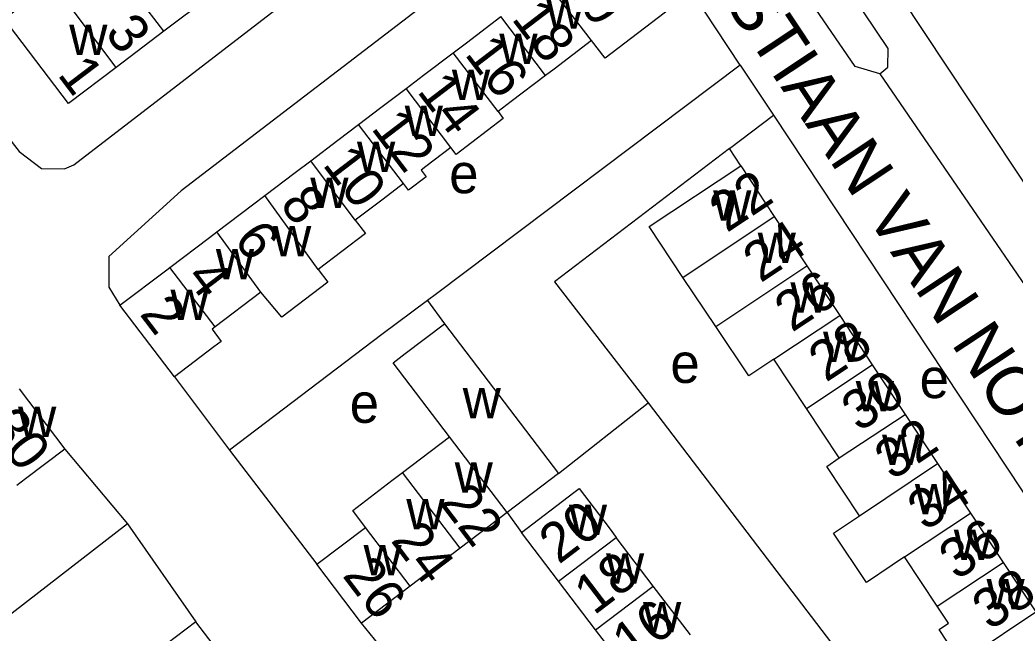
# Model space of a CAD drawing. Extents: x 159294 to 161936, y 384538 to 386517.
# Drawn here: x 160545.6 to 160646.3, y 385616.7 to 385678.8 of the extents above; entities that cross this region are included whole.
import ezdxf

# ---------------------------------------------------------------- set-up
doc = ezdxf.new("R2010")
doc.units = 0
for name, color, linetype in [('BLT_Basislijn', 7, 'Continuous'), ('BLT_Bebouwing', 7, 'Continuous'), ('BLT_Centroide', 7, 'Continuous'), ('BLT_Huisnummer', 7, 'Continuous'), ('BLT_Huisnummer_ tussenligend', 7, 'Continuous'), ('BLT_Onderverdeling_panden', 7, 'Continuous'), ('BLT_Straatnaam', 7, 'Continuous')]:
    doc.layers.add(name, color=color, linetype=linetype)

msp = doc.modelspace()

# ---------------------------------------------------------------- linework, layer by layer
at = {"layer": 'BLT_Basislijn'}
for p, q in [((160614.12, 385712.33), (160652.81, 385653.8)), ((160621.87, 385669.13), (160661.46, 385609.26)), ((160586.82, 385650.35), (160588.57, 385648.01)), ((160561.21, 385642.62), (160566.8, 385635.19)), ((160600.1, 385632.84), (160609.18, 385639.98)), ((160609.18, 385639.98), (160643.03, 385595.64)), ((160550.12, 385635.3), (160556.46, 385627.73)), ((160566.8, 385635.19), (160575.64, 385623.64)), ((160594.89, 385628.88), (160596.35, 385626.86)), ((160556.46, 385627.73), (160563.39, 385617.82))]:
    msp.add_line(p, q, dxfattribs=at)
for points in [[(160632.62, 385673.31), (160633.46, 385673.99), (160633.47, 385675.88), (160618.35, 385698.41), (160617.55, 385699.02), (160616.69, 385698.62), (160614.58, 385696.77)], [(160632.62, 385673.31), (160630.13, 385674.05), (160614.58, 385696.77)], [(160532.44, 385682.31), (160545.5, 385665.46), (160547.76, 385663.73), (160550.07, 385663.68), (160551.02, 385664.1), (160586.59, 385691.5), (160587.15, 385692.07)], [(160618.51, 385674.18), (160607.54, 385690.84), (160605.7, 385692.47), (160603.08, 385692.63), (160599.58, 385690.36), (160561.89, 385661.48), (160554.58, 385654.82), (160554.58, 385651.72), (160555.69, 385649.88)], [(160618.51, 385674.18), (160587.75, 385651.05), (160586.82, 385650.35)], [(160618.51, 385674.18), (160621.87, 385669.13)], [(160632.62, 385673.31), (160651.04, 385646.48), (160650.69, 385642), (160655.84, 385634.31)], [(160617.4, 385665.74), (160621.87, 385669.13)], [(160617.4, 385665.74), (160599.68, 385652.26), (160609.18, 385639.98)], [(160618.56, 385663.99), (160617.4, 385665.74)], [(160586.82, 385650.35), (160582.22, 385646.93), (160566.8, 385635.19)], [(160556.46, 385627.73), (160500, 385584), (160498.36, 385582.75)], [(160592.36, 385601.72), (160581.48, 385616.05), (160580.16, 385617.69)]]:
    msp.add_lwpolyline(points, dxfattribs=at)
at = {"layer": 'BLT_Bebouwing'}
for p, q in [((160564.99, 385681.29), (160560.15, 385677.63)), ((160590.78, 385676.47), (160594.26, 385679.11)), ((160560.15, 385677.63), (160555.32, 385673.96)), ((160603.44, 385676.69), (160599.65, 385673.8)), ((160589.43, 385675.45), (160590.78, 385676.47)), ((160586.44, 385673.18), (160589.43, 385675.45)), ((160599.65, 385673.8), (160598.79, 385673.15)), ((160584.66, 385671.84), (160586.44, 385673.18)), ((160598.79, 385673.15), (160595.32, 385670.51)), ((160582.11, 385669.9), (160584.66, 385671.84)), ((160579.85, 385668.18), (160582.11, 385669.9)), ((160595.32, 385670.51), (160593.98, 385669.49)), ((160577.77, 385666.61), (160579.85, 385668.18)), ((160575.01, 385664.52), (160577.77, 385666.61)), ((160589.21, 385665.86), (160586.66, 385663.92)), ((160573.43, 385663.33), (160575.01, 385664.52)), ((160618.56, 385663.99), (160621.95, 385658.86)), ((160570.35, 385660.99), (160573.43, 385663.33)), ((160584.4, 385662.2), (160582.33, 385660.62)), ((160569.1, 385660.04), (160570.35, 385660.99)), ((160582.33, 385660.62), (160579.52, 385658.48)), ((160565.5, 385657.31), (160569.1, 385660.04)), ((160579.52, 385658.48), (160580.55, 385657.13)), ((160621.95, 385658.86), (160625.26, 385653.86)), ((160560.74, 385653.7), (160564.76, 385656.75)), ((160564.76, 385656.75), (160565.5, 385657.31)), ((160580.55, 385657.13), (160575.77, 385653.5)), ((160555.69, 385649.88), (160560.43, 385653.47)), ((160560.43, 385653.47), (160560.74, 385653.7)), ((160625.26, 385653.86), (160628.57, 385648.85)), ((160569.97, 385651.21), (160565.33, 385647.68)), ((160561.21, 385642.62), (160555.69, 385649.88)), ((160628.57, 385648.85), (160631.87, 385643.85)), ((160565.33, 385647.68), (160565.02, 385647.44)), ((160588.57, 385648.01), (160600.1, 385632.84)), ((160625.22, 385639.41), (160621.91, 385644.41)), ((160631.87, 385643.85), (160635.2, 385638.82)), ((160545.48, 385641.41), (160550.12, 385635.3)), ((160628.52, 385634.41), (160625.22, 385639.41)), ((160635.2, 385638.82), (160638.49, 385633.84)), ((160584.31, 385632.93), (160589.06, 385636.54)), ((160638.49, 385633.84), (160641.8, 385628.83)), ((160600.1, 385632.84), (160594.89, 385628.88)), ((160594.89, 385628.88), (160590.13, 385625.26)), ((160641.8, 385628.83), (160645.11, 385623.83)), ((160575.64, 385623.64), (160580.56, 385627.38)), ((160609.7, 385621.44), (160605.94, 385626.37)), ((160590.13, 385625.26), (160585.08, 385621.43)), ((160638.45, 385619.39), (160635.14, 385624.39)), ((160580.16, 385617.69), (160575.64, 385623.64)), ((160645.11, 385623.83), (160648.42, 385618.82)), ((160585.08, 385621.43), (160580.16, 385617.69)), ((160603.86, 385617), (160600.11, 385621.93)), ((160613.45, 385616.51), (160609.7, 385621.44)), ((160569.69, 385609.54), (160563.39, 385617.82)), ((160607.62, 385612.07), (160603.86, 385617))]:
    msp.add_line(p, q, dxfattribs=at)
for points in [[(160555.32, 385673.96), (160550.49, 385670.3), (160545.8, 385676.48), (160543.98, 385678.89), (160548.94, 385682.64), (160550.64, 385680.15)], [(160611.5, 385679.99), (160604.81, 385674.9), (160603.44, 385676.69)], [(160594.5, 385668.78), (160589.75, 385665.15), (160589.21, 385665.86)], [(160593.98, 385669.49), (160594.5, 385668.78)], [(160586.66, 385663.92), (160586.18, 385663.55), (160586.69, 385662.88), (160584.92, 385661.52), (160584.4, 385662.2)], [(160612.69, 385652.69), (160609.28, 385657.85), (160618.56, 385663.99)], [(160575.77, 385653.5), (160576.75, 385652.22), (160572.08, 385648.67), (160569.97, 385651.21)], [(160616.04, 385647.71), (160612.69, 385652.69)], [(160565.02, 385647.44), (160565.94, 385646.22), (160565.19, 385645.65), (160561.21, 385642.62)], [(160589.06, 385636.54), (160583.36, 385644.04), (160584.59, 385644.98), (160588.57, 385648.01)], [(160621.91, 385644.41), (160619.37, 385642.72), (160616.04, 385647.71)], [(160550.12, 385635.3), (160546.14, 385632.28), (160545.27, 385631.62)], [(160630.57, 385628.55), (160627.26, 385633.56), (160628.52, 385634.41)], [(160580.56, 385627.38), (160579.26, 385629.09), (160583.24, 385632.11), (160584.31, 385632.93)], [(160601.65, 385630.9), (160602.19, 385631.3), (160605.22, 385627.32), (160605.94, 385626.37)], [(160600.11, 385621.93), (160596.35, 385626.86), (160601.65, 385630.9)], [(160635.14, 385624.39), (160633.88, 385623.55), (160631.27, 385621.81), (160627.94, 385626.8), (160630.57, 385628.55)], [(160641.76, 385614.38), (160640.83, 385613.69), (160638.63, 385617.02), (160639.59, 385617.66), (160638.45, 385619.39)], [(160563.39, 385617.82), (160558.48, 385614.09), (160560.18, 385612.02)]]:
    msp.add_lwpolyline(points, dxfattribs=at)
at = {"layer": 'BLT_Onderverdeling_panden'}
for p, q in [((160560.15, 385677.63), (160555.47, 385683.81)), ((160603.44, 385676.69), (160598.91, 385682.64)), ((160555.32, 385673.96), (160550.64, 385680.15)), ((160598.79, 385673.15), (160594.26, 385679.11)), ((160593.98, 385669.49), (160589.43, 385675.45)), ((160589.21, 385665.86), (160584.66, 385671.84)), ((160584.4, 385662.2), (160579.85, 385668.18)), ((160579.52, 385658.48), (160575.01, 385664.52)), ((160575.77, 385653.5), (160570.35, 385660.99)), ((160612.69, 385652.69), (160621.95, 385658.86)), ((160569.97, 385651.21), (160565.5, 385657.31)), ((160565.33, 385647.68), (160560.74, 385653.7)), ((160616.04, 385647.71), (160625.26, 385653.86)), ((160621.91, 385644.41), (160628.57, 385648.85)), ((160625.22, 385639.41), (160631.87, 385643.85)), ((160628.52, 385634.41), (160635.2, 385638.82)), ((160594.89, 385628.88), (160589.06, 385636.54)), ((160630.57, 385628.55), (160638.49, 385633.84)), ((160590.13, 385625.26), (160584.31, 385632.93)), ((160635.14, 385624.39), (160641.8, 385628.83)), ((160585.08, 385621.43), (160580.56, 385627.38)), ((160600.11, 385621.93), (160605.94, 385626.37)), ((160638.45, 385619.39), (160645.11, 385623.83)), ((160603.86, 385617), (160609.7, 385621.44)), ((160641.76, 385614.38), (160648.42, 385618.82))]:
    msp.add_line(p, q, dxfattribs=at)

# ---------------------------------------------------------------- texts
at = {"layer": 'BLT_Centroide'}
for s, p in [('w', (160598.84, 385677.89)), ('w', (160550.56, 385675.22)), ('w', (160594.11, 385674.3)), ('w', (160589.31, 385670.66)), ('w', (160584.53, 385667.02)), ('w', (160579.7, 385663.36)), ('e', (160589.03, 385661.22)), ('w', (160574.97, 385659.73)), ('w', (160615.76, 385658.44)), ('w', (160571.2, 385654.84)), ('w', (160620.27, 385654.16)), ('w', (160565.41, 385652.5)), ('w', (160560.81, 385648.38)), ('w', (160623.58, 385649.12)), ('w', (160626.89, 385644.12)), ('e', (160611.43, 385642.01)), ('e', (160636.66, 385640.47)), ('w', (160590.4, 385638.44)), ('w', (160630.2, 385639.12)), ('e', (160578.96, 385637.97)), ('w', (160545.38, 385636.52)), ('w', (160632.86, 385633.69)), ('w', (160589.59, 385630.91)), ('w', (160636.19, 385628.69)), ('w', (160584.69, 385627.17)), ('w', (160601.15, 385626.62)), ('w', (160640.12, 385624.09)), ('w', (160580.36, 385622.53)), ('w', (160604.91, 385621.69)), ('w', (160643.44, 385619.09)), ('w', (160608.66, 385616.75))]:
    msp.add_text(s, height=4, dxfattribs=at).set_placement(p)
at = {"layer": 'BLT_Huisnummer'}
for s, rotation, p in [('20', 307.2903, (160600.33, 385682.63)), ('1', 307.1551, (160549.29, 385673.24)), ('14', 307.2861, (160585.7, 385671.54)), ('10', 307.2847, (160576.13, 385664.12)), ('22', 33.4657, (160617.13, 385657.17)), ('6', 307.2879, (160567.12, 385656.48)), ('26', 33.4657, (160623.74, 385647.08)), ('2', 307.2882, (160557.61, 385648.98)), ('30', 33.4657, (160630.52, 385636.97)), ('30', 307.2403, (160542.11, 385637.55)), ('34', 33.4657, (160637.21, 385626.94)), ('22', 307.239, (160587.96, 385629.88)), ('20', 37.2903, (160600.13, 385623.57)), ('26', 307.2409, (160578.14, 385622.49)), ('38', 33.4657, (160643.76, 385616.87)), ('16', 37.2936, (160607.53, 385613.58))]:
    msp.add_text(s, height=4, rotation=rotation, dxfattribs=at).set_placement(p)
at = {"layer": 'BLT_Huisnummer_ tussenligend'}
for s, rotation, p in [('18', 307.2861, (160595.27, 385678.89)), ('3', 307.1551, (160554.08, 385677.44)), ('16', 307.2861, (160590.52, 385675.3)), ('12', 307.2847, (160581.05, 385667.79)), ('8', 307.2879, (160571.79, 385660.07)), ('24', 33.4657, (160620.55, 385652.09)), ('4', 307.2882, (160562.27, 385652.67)), ('28', 33.4657, (160627.18, 385642.02)), ('32', 33.4657, (160633.88, 385632.07)), ('36', 33.4657, (160640.4, 385621.95)), ('24', 307.239, (160583.04, 385626.04)), ('18', 37.2936, (160603.69, 385618.41))]:
    msp.add_text(s, height=4, rotation=rotation, dxfattribs=at).set_placement(p)
at = {"layer": 'BLT_Straatnaam'}
msp.add_text('SEBASTIAAN VAN NOYESTRAAT', height=5, rotation=303.5727, dxfattribs=at).set_placement((160606.92, 385695.53))

doc.saveas('drawing.dxf')
